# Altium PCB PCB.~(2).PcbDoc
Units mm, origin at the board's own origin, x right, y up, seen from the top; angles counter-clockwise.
Board outline 75.31 x 77.22 mm, 2 copper layers (Top Layer, Bottom Layer); 67 components, 24 nets, 314 pads, 26 vias.
Unrouted connection lines stored in the file: 1.
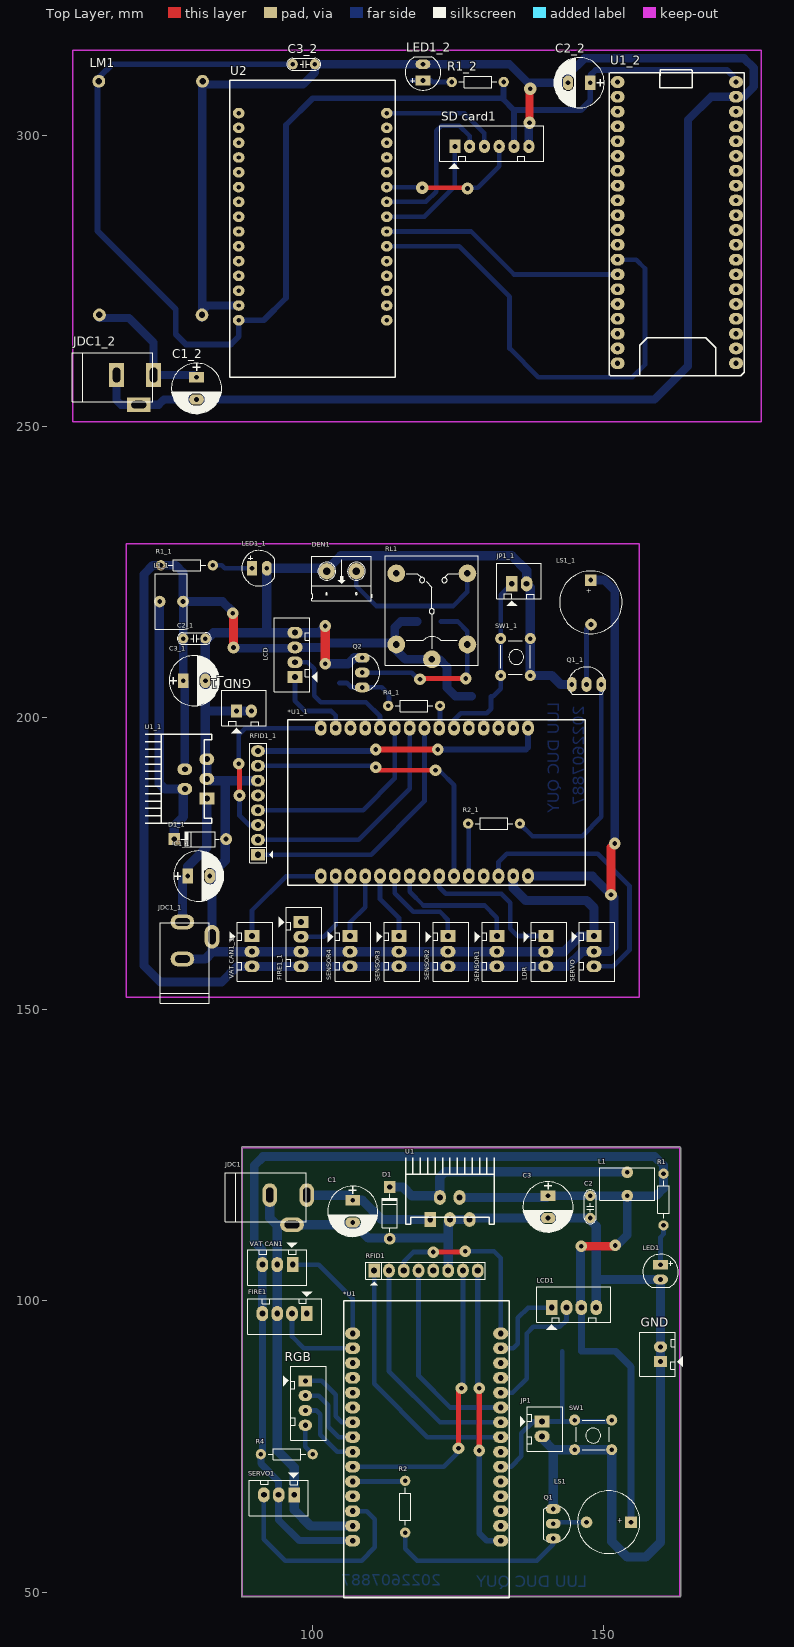
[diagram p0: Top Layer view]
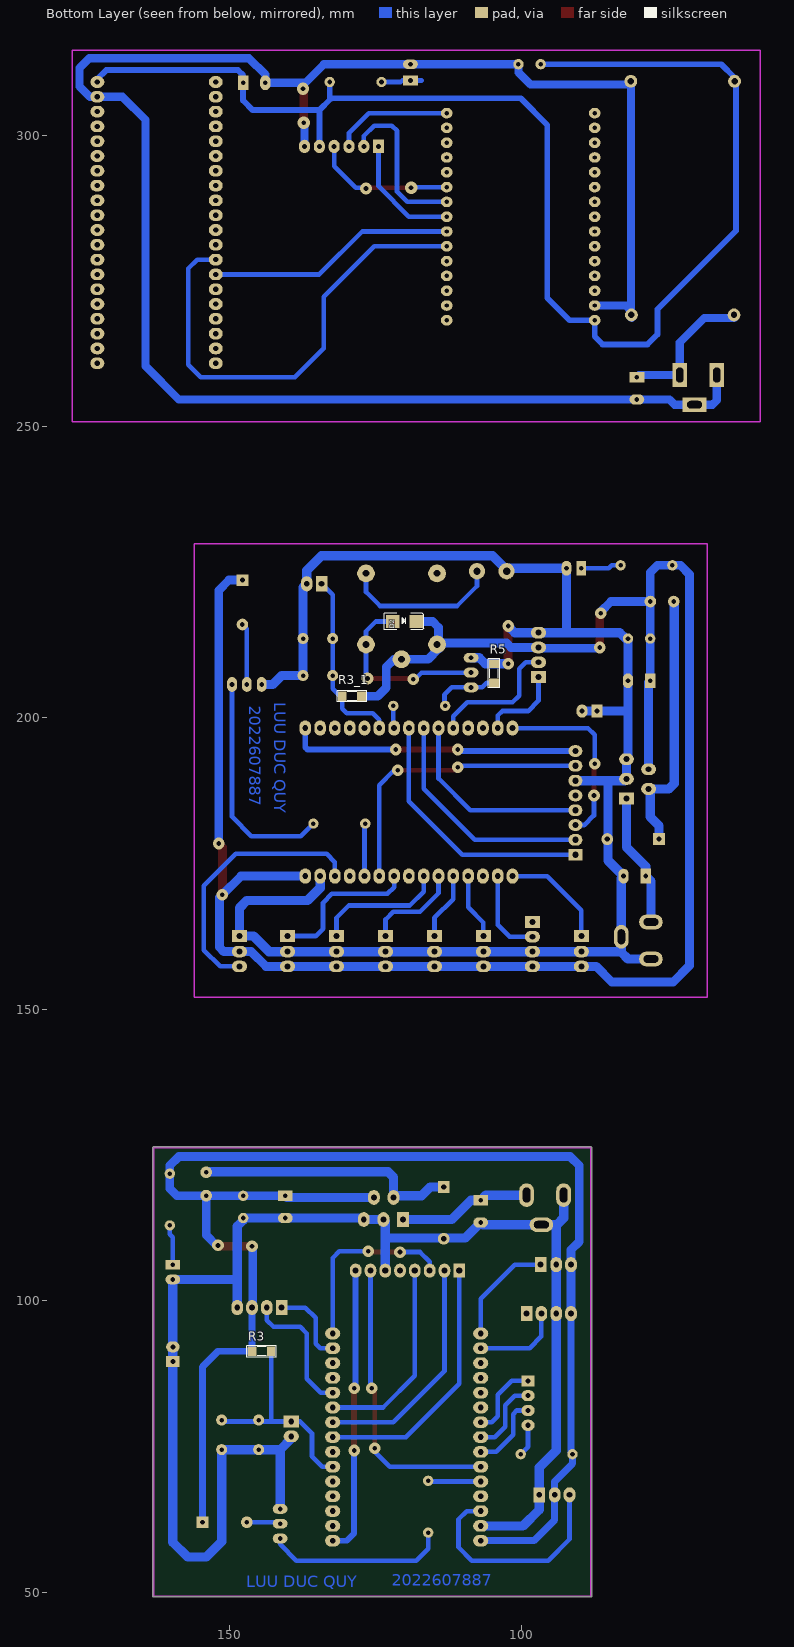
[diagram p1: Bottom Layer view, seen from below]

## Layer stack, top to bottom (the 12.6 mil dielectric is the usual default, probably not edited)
Top Solder: solder mask 0.0102, Solder Resist, Dk 3.5
Top Layer: signal copper 0.0356
Dielectric 1: dielectric 0.32, FR-4, Dk 4.8
Bottom Layer: signal copper 0.0356
Bottom Solder: solder mask 0.0102, Solder Resist, Dk 3.5

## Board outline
87.884,49.276 ccw(c88.011,49.276) 88.011,49.149 163.068,49.149 ccw(c163.068,49.276) 163.195,49.276 163.195,126.238 ccw(c163.068,126.238) 163.068,126.365 88.011,126.365 ccw(c88.011,126.238) 87.884,126.238

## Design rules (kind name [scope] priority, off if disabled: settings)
Clearance [All] p1: gap=0.254 ignorepadtopadclearanceinfootprint=FALSE except(0: Arc-Hole Track-Hole SMDPad-Hole THPad-Hole Via-Hole Fill-Hole Poly-Hole Region-Hole Text-Hole)
PolygonConnect [All] p1: connectstyle=Relief reliefconductorwidth=0.254 reliefentries=4 polygonreliefangle="90 Angle" airgapwidth=0.254
RoutingVias [All] p1: holewidth=0.711 width=1.27 viastyle="Through Hole" minholewidth=0.711 minwidth=1.27 maxholewidth=0.711 maxwidth=1.27
SolderMaskExpansion [All] p1: expansion=0.102
Width GND [InNet('GND')] p1: maxlimit=1.6 minlimit=0.254 preferedwidth=1.6
Width 12V [InNet('12V')] p2: maxlimit=1.6 minlimit=0.254 preferedwidth=1.6
Width 3V3 [InNet('3V3')] p3: maxlimit=1 minlimit=0.254 preferedwidth=1
Width 5V [InNet('5V')] p4: maxlimit=3 minlimit=0.254 preferedwidth=1.2
Width NET [All] p5: maxlimit=3 minlimit=0.254 preferedwidth=0.8
30 further rules are at their usual default settings.

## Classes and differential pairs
component class schematic: *U1 C1 C2 C3 D1 FIRE1 GND JDC1 JP1 L1 LCD1 LED1 LS1 Q1 R1 R2 R3 R4 RFID1 RGB SERVO1 SW1 U1 "VAT CAN1"

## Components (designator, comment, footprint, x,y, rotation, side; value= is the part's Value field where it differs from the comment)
*U1 "*ESP32 module" "ESP32 Module 30PIN"#1 129.794,58.801 r90 top
*U1_1 "*ESP32 module" "ESP32 Module 30PIN"#1 137.033,195.707 r180 top (schematic designator *U1)
C1 "1000uF/16V" CP1.5/3.4 106.934,117.221 r270 top
C1_1 "1000uF/16V" CP1.5/3.4 78.613,172.847 r0 top (schematic designator C1)
C1_2 "1000uF/16V" CP1.5/3.4 80.137,258.445 r270 top (schematic designator C1)
C2 "103" CN1.5 147.701,114.173 r90 top value=0.01uF
C2_1 "103" CN1.5 81.661,213.614 r180 top value=0.01uF (schematic designator C2)
C2_2 "1000uF/16V" CP1.5/3.4 147.701,308.991 r180 top (schematic designator C2)
C3 "1000uF/16V" CP1.5/3.4 140.462,117.983 r270 top
C3_1 "1000uF/16V" CP1.5/3.4 77.851,206.375 r0 top (schematic designator C3)
C3_2 "103" CN1.5 100.457,312.166 r180 top value=0.01uF (schematic designator C3)
D1 "1N4007" D1A 113.284,110.617 r270 top
D1_1 "1N4007" D1A 85.217,179.197 r0 top (schematic designator D1)
D2 "1N4007" DIO-SMD-106 120.015,216.535 r0 bottom
DEN1 "Header 2" HED2 107.569,225.171 r180 top
FIRE1 "JP4" CON4#1 99.06,97.769 r180 top value="Connector 4"
FIRE1_1 "JP4" CON4#1 98.065,164.973 r270 top value="Connector 4" (schematic designator FIRE1)
GND "JP2" CON2#1 159.766,89.535 r90 top value="Connector 2"
GND_1 "JP2" CON2#1 86.995,201.168 r0 top value="Connector 2" (schematic designator GND)
JDC1 "Jac DC" DC0 95.885,115.57 r0 top
JDC1_1 "Jac DC" DC0 80.264,161.798 r90 top (schematic designator JDC1)
JDC1_2 "Jac DC" DC-IN 69.596,256.286 r0 top (schematic designator JDC1)
JP1 "JP2" CON2#2 139.446,79.248 r270 top value="Connector 2"
JP1_1 "JP2" CON2#2 134.239,223.012 r0 top value="Connector 2" (schematic designator JP1)
L1 "L-DIP-1" L-DIP-M-9.5x5.5 154.051,120.015 r270 top value="150 mH"
L1_1 "L-DIP-1" L-DIP-M-9.5x5.5 75.819,219.964 r0 top value="150 mH" (schematic designator L1)
LCD "JP4" CON4#1 97.028,207.01 r90 top value="Connector 4"
LCD1 "JP4" CON4#1 141.097,98.806 r0 top value="Connector 4"
LDR "JP3" CON3 140.081,162.433 r270 top value="Connector 3"
LED1 "LED" LED-5-Green 159.766,106.172 r270 top value="LED 3 ly Single Colour"
LED1_1 "LED" LED-5-Green 89.662,225.679 r0 top value="LED 3 ly Single Colour" (schematic designator LED1)
LED1_2 "LED" LED-5-BLUE 118.999,310.769 r90 top value="LED 3 ly Single Colour" (schematic designator LED1)
LM1 "LM2596 module" LM2596module 81.073,269.145 r90 top
LS1 "Speaker" SPEAKER 154.686,61.976 r180 top
LS1_1 "Speaker" SPEAKER 147.815,223.647 r270 top (schematic designator LS1)
Q1 "C1815" QTO-92 141.351,61.722 r270 top
Q1_1 "C1815" QTO-92 147.066,205.74 r0 top (schematic designator Q1)
Q2 "C1815" QTO-92 108.585,207.772 r270 top
R1 "1k" R1/4W 160.274,121.793 r270 top value="R1/4W - 1K"
R1_1 "1k" R1/4W 74.041,226.187 r0 top value="R1/4W - 1K" (schematic designator R1)
R1_2 "1k" R1/4W 123.952,309.118 r0 top value="R1/4W - 1K" (schematic designator R1)
R2 "1k" R1/4W 115.951,69.088 r270 top value="R1/4W - 1K"
R2_1 "1k" R1/4W 126.746,181.864 r0 top value="R1/4W - 1K" (schematic designator R2)
R3 "10k" SM-RES-1206 142.875,91.313 r0 bottom value="R1/4W - 1K"
R3_1 "10k" SM-RES-1206 130.683,203.708 r180 bottom value="R1/4W - 1K" (schematic designator R3)
R4 "330r" R1/4W 91.186,73.66 r0 top value="R1/4W - 1K"
R4_1 "1k" R1/4W 121.92,202.057 r180 top value="R1/4W - 1K" (schematic designator R4)
R5 "10k" SM-RES-1206 104.648,209.296 r270 bottom value="R1/4W - 1K"
RFID1 "RFID RC522" JP8 110.617,105.156 r0 top
RFID1_1 "RFID RC522" JP8 90.678,176.53 r90 top (schematic designator RFID1)
RGB "JP4" CON4#2 98.806,86.233 r270 top value="Connector 4"
RL1 "Relay 10A/12V" RL_SPDT_10A 120.523,210.058 r90 top value="Relay SPDT, 10A, 12V"
"SD card1" "JP6" CON6 124.46,298.069 r0 top value="Connector 6"
SENSOR1 "JP3" CON3 131.678,162.433 r270 top value="Connector 3"
SENSOR2 "JP3" CON3 123.275,162.433 r270 top value="Connector 3"
SENSOR3 "JP3" CON3 114.872,162.433 r270 top value="Connector 3"
SENSOR4 "JP3" CON3 106.468,162.433 r270 top value="Connector 3"
SERVO "JP3" CON3 148.336,162.433 r270 top value="Connector 3"
SERVO1 "JP3" CON3 96.774,66.675 r180 top value="Connector 3"
SW1 "SW" SW4 151.384,74.422 r180 top value="Button chip 4 pin"
SW1_1 "SW" SW4 137.414,213.614 r270 top value="Button chip 4 pin" (schematic designator SW1)
U1 "LM2576" DIP5-T 123.596,118.161 r0 top
U1_1 "LM2576" DIP5-T 77.673,189.509 r90 top (schematic designator U1)
U1_2 "TANG NANO 20K" "TANG NANO" 152.4,258.318 r0 top (schematic designator U1)
U2 "*ESP32 module" "ESP32 Module 30PIN"#2 110.236,268.224 r90 top
"VAT CAN1" "JP3" CON3 96.52,106.172 r180 top value="Connector 3"
"VAT CAN1_1" "JP3" CON3 89.662,162.433 r270 top value="Connector 3" (schematic designator "VAT CAN1")

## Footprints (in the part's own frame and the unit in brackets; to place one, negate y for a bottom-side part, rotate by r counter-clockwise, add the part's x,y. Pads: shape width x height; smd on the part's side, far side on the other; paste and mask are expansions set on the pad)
CN1.5 [mil]
  round 70 hole 31: 1(0,0) 2(150,0)
  silkscreen extent -40,-40 190,40, body extent -40,-33 190,33, height 235
CON2#1 [mil] "CON2"
  rect 75x90 hole 34: 1(0,0)
  oval 75x90 hole 34: 2(100,0)
  silkscreen extent -100,-150 200,140, body extent -68,-70 168,107, height 236
CON2#2 [mil] "CON2"
  rect 78.74x102.36 hole 39.37: 1(0,0)
  oval 78.74x102.36 hole 39.37: 2(100,0)
  silkscreen extent -100,-150 200,140, body extent -68,-70 168,107, height 236
CON3 [mm] "CON 3"
  rect 2x2.6 hole 1: 1(-0.127,0)
  oval 2x2.6 hole 1: 2(2.54,0) 3(5.08,0)
  silkscreen extent -2.54,-3.8 7.62,3.56, body extent -2.41,-2.29 7.49,3.46, height 7
CON4#1 [mm] "CON4"
  rect 2x2.6 hole 1: 1(0,0)
  oval 2x2.6 hole 1: 2(2.54,0) 3(5.08,0) 4(7.62,0)
  silkscreen extent -2.54,-3.8 10.16,3.56, body extent -2.29,-2.29 10.11,3.46, height 7
CON4#2 [mm] "CON4"
  rect 1.905x2.286 hole 0.864: 1(0,0)
  oval 1.905x2.286 hole 0.864: 2(2.54,0) 3(5.08,0) 4(7.62,0)
  silkscreen extent -2.54,-3.8 10.16,3.56, body extent -2.29,-2.29 10.11,3.46, height 7
CON6 [mil] "CON6"
  rect 75x90 hole 34: 1(0,0)
  oval 75x90 hole 34: 2(100,0) 3(200,0) 4(300,0) 5(400,0) 6(500,0)
  silkscreen extent -100,-150 600,140
CP1.5/3.4 [mil] "Tu hoa 220->470uF,16V, 470uF/16V,25V"
  rect 70x100 hole 32: 1(0,0)
  oval 70x100 hole 32: 2(150,0)
  silkscreen extent -95,-170 245,170, body extent -85,-157 230,157, height 446
D1A [mil] "Diode 1A, W 100mil, L 350mil"
  round 80 hole 35: 1(0,0)
  rect 80x80 hole 35: 2(-350,0)
  silkscreen extent -305,-50 -45,50, body extent -386,-33 34,36, height 84
DC0 [mil] "Jac DC input"
  oval 100x160 hole 50 slot 100 at 90 deg: 1(125,100) 2(-125,100)
  oval 160x100 hole 50 slot 100 at 0 deg: 3(25,-100)
  silkscreen extent -425,-80 120,250, body extent -410,-105 134,269, height 434
DC-IN [mil] "Jac DC input"
  rect 100x160 hole 50 slot 100 at 90 deg: 1(125,100) 2(-125,100)
  rect 160x100 hole 50 slot 100 at 0 deg: 3(25,-100)
  silkscreen extent -425,-80 120,250, body extent -410,-105 134,269, height 434
DIO-SMD-106 [mil]
  rect 90x90.55 smd: 1(80,0) 2(-80,0)
  silkscreen extent -130,-55 135,55, body extent -99,-50 106,52, height 95
DIP5-T [mil]
  rect 80x100 hole 40: 1(-132,-167.09)
  oval 80x100 hole 40: 2(-67,-18) 3(1,-167) 4(66,-18) 5(134,-167)
  round 0 all layers, no hole: ""(1,100)
  silkscreen extent -299,-200 301,250, body extent -199,-175 201,150, height 859
"ESP32 Module 30PIN"#1 [mm]
  oval 2x2.6 hole 1 unplated: 1(0,-2.54) 2(2.54,-2.54) 3(5.08,-2.54) 4(7.62,-2.54) 5(10.16,-2.54) 6(12.7,-2.54) 7(15.24,-2.54) 8(17.78,-2.54) 9(20.32,-2.54) 10(22.86,-2.54) 11(25.4,-2.54) 12(27.94,-2.54) 13(30.48,-2.54) 14(33.02,-2.54) 15(35.56,-2.54) 16(35.56,22.86) 17(33.02,22.86) 18(30.48,22.86) 19(27.94,22.86) 20(25.4,22.86) 21(22.86,22.86) 22(20.32,22.86) 23(17.78,22.86) 24(15.24,22.86) 25(12.7,22.86) 26(10.16,22.86) 27(7.62,22.86) 28(5.08,22.86) 29(2.54,22.86) 30(0,22.86)
  silkscreen extent -9.8,-4 41.2,24.4, body extent -9.9,-4.15 41.03,24.35, height 10.2
"ESP32 Module 30PIN"#2 [mm]
  oval 1.8x2 hole 0.762 unplated: 1(0,-2.54) 2(2.54,-2.54) 3(5.08,-2.54) 4(7.62,-2.54) 5(10.16,-2.54) 6(12.7,-2.54) 7(15.24,-2.54) 8(17.78,-2.54) 9(20.32,-2.54) 10(22.86,-2.54) 11(25.4,-2.54) 12(27.94,-2.54) 13(30.48,-2.54) 14(33.02,-2.54) 15(35.56,-2.54) 16(35.56,22.86) 17(33.02,22.86) 18(30.48,22.86) 19(27.94,22.86) 20(25.4,22.86) 21(22.86,22.86) 22(20.32,22.86) 23(17.78,22.86) 24(15.24,22.86) 25(12.7,22.86) 26(10.16,22.86) 27(7.62,22.86) 28(5.08,22.86) 29(2.54,22.86) 30(0,22.86)
  silkscreen extent -9.8,-4 41.2,24.4, body extent -9.9,-4.15 41.03,24.35, height 10.2
HED2 [mil] "Header 2, 2 pin, hight 300mil, Pin to Pin 200, Colour Green"
  round 110 hole 50: 1(0,0) 2(200,0)
  silkscreen extent -106,-100 300,200, body extent -92,-140 302,155, height 394
JP8 [mm] "JP8"
  rect 2x2.4 hole 1.067: 1(0,0)
  oval 2x2.4 hole 1.067: 2(2.54,0) 3(5.08,0) 4(7.62,0) 5(10.16,0) 6(12.7,0) 7(15.24,0) 8(17.78,0)
  silkscreen extent -1.42,-2.54 19.1,1.45, body extent -1.22,-1.27 19,1.23, height 8.22
L-DIP-M-9.5x5.5 [mm] "Body 9.5x5.5mm, 2 leads"
  round 2 hole 0.8: 1(-2,0) 2(2,0)
  silkscreen extent -2.75,-4.75 2.75,4.75, body extent -2.57,-5.05 2.57,5.05, height 10.07
LED-5-BLUE [mil] "LED 2 PIN, 5 ly , Only colour, pin to pin 110mil"
  rect 65x100 hole 32: 1(-55,0)
  oval 65x100 hole 32: 2(55,0)
  silkscreen extent -120,-120 104,120, body extent -113,-120 100,117, height 339
LED-5-Green [mil] "LED 2 PIN, 5 ly , Only colour,pin to pin 100mil"
  rect 65x100 hole 32: 1(0,0)
  oval 65x100 hole 32: 2(100,0)
  silkscreen extent -70,-120 154,120, body extent -69,-120 145,117, height 339
LM2596module [mm]
  round 2.2 hole 1.1: 1(0,17.6) 2(0,0) 3(40.1,-0.1) 4(40.1,17.7)
  body extent -1.6,-1.8 41.7,19.5, height 12.95
QTO-92 [mil] "TO-92"
  oval 66x100 hole 32: 1(-100,0) 2(0,0) 3(100,0)
  silkscreen extent -117,-65 120,118, body extent -109,-66 109,95, height 245
R1/4W [mil] "R 1/4W, 2 Pin, 350mil"
  round 70 hole 31: 1(0,0) 2(350,0)
  silkscreen extent 48,-38 302,38, body extent -40,-47 386,47, height 111
RL_SPDT_10A [mil] "Relay SPDT, 5 pin, 10A,W 650mil, L 800mil, H 800mil"
  round 120 hole 45: 1(0,0) 2(580,240) 3(580,-240) 4(100,-240) 5(100,240)
  silkscreen extent -40,-315 700,315, body extent -46,-304 706,306, height 602
SM-RES-1206 [mil]
  rect 60x65 smd: 1(0,0) 2(130,0)
  silkscreen extent -34,-38 164,39, body extent 2,-31 128,31, height 40
SPEAKER [mm]
  rect 2x2 hole 0.8: 1(0,0)
  round 2 hole 0.8: 2(7.62,0.013)
  silkscreen extent -1.55,-5.38 9.18,5.36, body extent -2.22,-6 13.24,6, height 4.5
SW4 [mil] "SW button 4pin, 250 x250 mil"
  round 75 hole 31: 1(0,0) 2(250,-200) 3(250,0) 4(0,-200)
  silkscreen extent 15,-215 240,0, body extent -36,-220 276,24, height 276
"TANG NANO" [mm]
  oval 2.4x2 hole 0.9: 1(0,50.8) 2(0,48.26) 3(0,45.72) 4(0,43.18) 5(0,40.64) 6(0,38.1) 7(0,35.56) 8(0,33.02) 9(0,30.48) 10(0,27.94) 11(0,25.4) 12(0,22.86) 13(0,20.32) 14(0,17.78) 15(0,15.24) 16(0,12.7) 17(0,10.16) 18(0,7.62) 19(0,5.08) 20(0,2.54) 21(20.32,2.54) 22(20.32,5.08) 23(20.32,7.62) 24(20.32,10.16) 25(20.32,12.7) 26(20.32,15.24) 27(20.32,17.78) 28(20.32,20.32) 29(20.32,22.86) 30(20.32,25.4) 31(20.32,27.94) 32(20.32,30.48) 33(20.32,33.02) 34(20.32,35.56) 35(20.32,38.1) 36(20.32,40.64) 37(20.32,43.18) 38(20.32,45.72) 39(20.32,48.26) 40(20.32,50.8)
  silkscreen extent -1.4,0.4 21.7,52.9

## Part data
*U1 *U1_1 U2: library part "ESP32 module"
C1 C1_1 C1_2 C2_2 C3 C3_1: library part CP4, "Cap 1000uF/16V - 220uF/50V"
C2 C2_1 C3_2: library part CN1.5, "Cap np 682pF => 104pF"
D1 D1_1 D2: library part D1A, "Diode 1A"
DEN1: library part Hed2, "Header 2 (Green)"
FIRE1 FIRE1_1 LCD LCD1 RGB: library part Con4, "Connector 4"
GND GND_1 JP1 JP1_1: library part Con2, "Connector 2"
JDC1 JDC1_1 JDC1_2: library part DCIN, "Jac DC input"
L1 L1_1: "Inductor"
LDR SENSOR1 SENSOR2 SENSOR3 SENSOR4 SERVO SERVO1 "VAT CAN1" "VAT CAN1_1": library part Con3, "Connector 3"
LED1 LED1_1 LED1_2: "LED Single colour Green and Red"
LS1 LS1_1: "Loudspeaker"
Q1 Q1_1 Q2: "NPN 600mW, ECB"
R1 R1_1 R1_2 R2 R2_1 R4 R4_1: library part R1/4W, "Resistor 1/4W"
R3 R3_1 R5: library part R, "Resistor 1/4W"
RL1: library part "Relay 1", "Relay SPDT,10A - 12VDC 5 Pin"
"SD card1": library part Con6, "Connector 6"
SW1 SW1_1: library part SW4, "Switch button 4 pin"
U1 U1_1: Max Input Voltage="12 V", Max Output Current="3 (6.0 peak) A", Max Output Voltage=mV, Temperature Range="-40 to +125 degC"
U1_2: library part "Tang nano 20K"

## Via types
v1: diameter 2, hole 0.8, Top Layer to Bottom Layer, 22 vias
v2: diameter 2.1, hole 0.82, Top Layer to Bottom Layer, 4 vias

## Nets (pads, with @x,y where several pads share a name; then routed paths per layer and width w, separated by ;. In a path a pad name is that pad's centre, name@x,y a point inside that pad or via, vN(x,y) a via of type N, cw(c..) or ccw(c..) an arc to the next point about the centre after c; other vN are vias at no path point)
3V3: *U1.1 RFID1.8 | length 48.4
  Top Layer w1: v1(128.651,74.295) v1(128.651,84.963)
  Bottom Layer w1: v1@128.397,85.344 RFID1.8 ; v1@128.651,73.787 128.651,60.071 129.921,58.801 *U1.1
5V: "VAT CAN1.3" *U1.30 C2.2 C3.1 FIRE1.4 L1.2 LCD1.3 LS1.1 R1.1 R3.2 R4.1 SERVO1.2 U1.4 | length 256.9
  Top Layer w1.5: v1(146.177,109.347) 151.892,109.347 v1(152.019,109.474)
  Bottom Layer w1.2: FIRE1.4 91.44,73.914 R4.1 91.186,72.009 94.234,68.961 SERVO1.2 94.234,62.357 97.79,58.801 *U1.30 ; LCD1.3 R3.2 152.019,91.313 154.686,88.646 LS1.1
  Bottom Layer w1.5: FIRE1.4 91.44,106.172 91.44,108.712 90.043,110.109 90.043,123.19 91.567,124.714 158.75,124.714 160.274,123.19 R1.1 160.274,119.253 159.036,118.015 L1.2 ; U1.4 140.183,117.704 C3.1 C2.2 154.019,117.983 L1.2 ; v1@146.047,108.715 146.047,98.936 LCD1.3 ; v1@152.273,109.474 154.051,111.252 L1.2
12V: C1.1 JDC1.1 U1.1 | length 22.9
  Bottom Layer w1.6: JDC1.1 106.045,118.11 C1.1 108.585,117.221 111.889,113.917 U1.1
B_PIN: *U1.22 RGB.1 | length 13.2
  Bottom Layer w0.8: RGB.1 101.6,86.233 104.013,83.82 104.013,80.137 105.029,79.121 *U1.22
Buzzer: *U1.26 R2.1 | length 9.1
  Bottom Layer w0.8: *U1.26 115.824,68.961 R2.1
G_PIN: *U1.24 RGB.3 | length 13.2
  Bottom Layer w0.8: RGB.3 100.711,81.153 101.346,80.518 101.346,76.962 104.267,74.041 *U1.24
GND: "VAT CAN1.2" *U1.29 C1.2 C2.1 C3.2 D1.1 FIRE1.3 GND.1 GND.2 JDC1.2 JDC1.3 JP1.2 LCD1.4 LED1.2 Q1.1 RFID1.6 SERVO1.1 SW1.1 SW1.3 U1.3 U1.5 | length 252.3
  Bottom Layer w1.6: JDC1.2 92.71,114.173 93.853,113.03 94.234,113.03 ; *U1.29 99.695,61.341 96.901,64.135 SERVO1.1 96.901,71.374 93.98,74.295 FIRE1.3 93.98,106.172 93.98,112.776 94.234,113.03 ; RFID1.6 123.317,110.744 ; JP1.2 139.446,76.327 141.351,74.422 ; Q1.1 141.351,74.422 ; LCD1.4 148.717,103.378 ; 94.234,113.03 JDC1.3 106.553,113.03 C1.2 109.601,110.744 123.317,110.744 ; 123.317,110.744 123.317,113.614 U1.3 U1.5 127.254,114.173 C3.2 C2.1 147.701,113.792 148.717,112.776 148.717,103.378 ; 141.351,74.422 SW1.3 SW1.1 151.384,58.674 154.051,56.007 157.226,56.007 159.766,58.547 GND.1 GND.2 LED1.2 148.971,103.632 148.717,103.378
LCD_SCL: *U1.14 LCD1.1 | length 14.3
  Bottom Layer w0.8: *U1.14 134.493,91.821 135.255,92.583 135.255,97.028 137.033,98.806 LCD1.1
LCD_SDA: *U1.11 LCD1.2 | length 23.2
  Bottom Layer w0.8: *U1.11 134.366,84.201 136.779,86.614 136.779,94.361 137.922,95.504 142.494,95.504 143.637,96.647 LCD1.2
NetD1_2: D1.2 L1.1 U1.2 | length 45.5
  Bottom Layer w1.6: D1.2 115.57,119.507 117.094,117.983 121.615,117.983 U1.2 121.895,121.158 122.841,122.105 154.051,122.105 L1.1
NetLED1_1: LED1.1 R1.2 | length 6.9
  Bottom Layer w0.8: LED1.1 159.766,110.871 160.274,111.379 R1.2
NetLS1_2: LS1.2 Q1.2 | length 5.8
  Bottom Layer w0.8: Q1.2 141.592,61.963 LS1.2
NetQ1_3: Q1.3 R2.2 | length 31.2
  Bottom Layer w0.8: R2.2 115.951,57.404 117.983,55.372 138.557,55.372 141.351,58.166 Q1.3
NetR4_2: R4.2 RGB.4 | length 5.5
  Bottom Layer w0.8: RGB.4 98.806,74.93 R4.2
"PIN_BTN MANUAL": *U1.6 JP1.1 R3.1 SW1.2 SW1.4 | length 36.5
  Bottom Layer w0.8: *U1.6 134.112,71.501 135.89,73.279 135.89,77.216 137.922,79.248 JP1.1 142.875,79.248 ; R3.1 142.875,79.248 ; SW1.4@151.257,79.248 142.875,79.248
PIN_FIRE: *U1.17 FIRE1.2 | length 15.2
  Bottom Layer w0.8: FIRE1.2 96.52,93.853 98.552,91.821 *U1.17
PIN_VATCAN: "VAT CAN1.1" *U1.19 | length 18.7
  Bottom Layer w0.8: 96.647,106.172 101.092,106.172 106.934,100.33 106.934,94.361
R_PIN: *U1.23 RGB.2 | length 13.2
  Bottom Layer w0.8: RGB.2 101.092,83.693 102.743,82.042 102.743,78.359 104.521,76.581 *U1.23
RFID_MISO: *U1.10 RFID1.4 | length 34.4
  Bottom Layer w0.8: RFID1.4 118.237,87.122 123.698,81.661 *U1.10
RFID_MOSI: *U1.15 RFID1.3 | length 32.3
  Top Layer w0.8: v1(120.777,108.331) 126.111,108.331 v1(126.238,108.458)
  Bottom Layer w0.8: RFID1.3 115.697,106.68 117.348,108.331 v1(120.777,108.331) ; v1(126.238,108.458) 131.191,108.458 132.334,107.315 *U1.15
RFID_RST: *U1.25 RFID1.7 | length 50.7
  Top Layer w0.8: v1(125.095,74.676) 125.095,84.455 v1(125.603,84.963)
  Bottom Layer w0.8: *U1.25 122.555,71.501 124.968,73.914 v1@124.968,74.676 ; v1@125.857,84.709 RFID1.7
RFID_SCK: *U1.9 RFID1.2 | length 40.1
  Bottom Layer w0.8: RFID1.2 113.157,87.884 121.92,79.121 *U1.9
RFID_SS: *U1.8 RFID1.1 | length 44.9
  Bottom Layer w0.8: RFID1.1 110.617,85.725 119.761,76.581 *U1.8
servo: *U1.28 SERVO1.3 | length 38.4
  Bottom Layer w0.8: SERVO1.3 91.694,59.055 95.377,55.372 108.458,55.372 110.744,57.658 110.744,62.484 109.347,63.881 *U1.28
pads on no net: "SD card1.1" "SD card1.2" "SD card1.3" "SD card1.4" "SD card1.5" "SD card1.6" "VAT CAN1_1.1" "VAT CAN1_1.2" "VAT CAN1_1.3" *U1.2 *U1.3 *U1.4 *U1.5 *U1.7 *U1.12 *U1.13 *U1.16 *U1.18 *U1.20 *U1.21 *U1.27 *U1_1.1 *U1_1.2 *U1_1.3 *U1_1.4 *U1_1.5 *U1_1.6 *U1_1.7 *U1_1.8 *U1_1.9 *U1_1.10 *U1_1.11 *U1_1.12 *U1_1.13 *U1_1.14 *U1_1.15 *U1_1.16 *U1_1.17 *U1_1.18 *U1_1.19 *U1_1.20 *U1_1.21 *U1_1.22 *U1_1.23 *U1_1.24 *U1_1.25 *U1_1.26 *U1_1.27 *U1_1.28 *U1_1.29 *U1_1.30 C1_1.1 C1_1.2 C1_2.1 C1_2.2 C2_1.1 C2_1.2 C2_2.1 C2_2.2 C3_1.1 C3_1.2 C3_2.1 C3_2.2 D1_1.1 D1_1.2 D2.1 D2.2 DEN1.1 DEN1.2 FIRE1.1 FIRE1_1.1 FIRE1_1.2 FIRE1_1.3 FIRE1_1.4 GND_1.1 GND_1.2 JDC1_1.1 JDC1_1.2 JDC1_1.3 JDC1_2.1 JDC1_2.2 JDC1_2.3 JP1_1.1 JP1_1.2 L1_1.1 L1_1.2 LCD.1 LCD.2 LCD.3 LCD.4 LDR.1 LDR.2 LDR.3 LED1_1.1 LED1_1.2 LED1_2.1 LED1_2.2 LM1.1 LM1.2 LM1.3 LM1.4 LS1_1.1 LS1_1.2 Q1_1.1 Q1_1.2 Q1_1.3 Q2.1 Q2.2 Q2.3 R1_1.1 R1_1.2 R1_2.1 R1_2.2 R2_1.1 R2_1.2 R3_1.1 R3_1.2 R4_1.1 R4_1.2 R5.1 R5.2 RFID1.5 RFID1_1.1 RFID1_1.2 RFID1_1.3 RFID1_1.4 RFID1_1.5 RFID1_1.6 RFID1_1.7 RFID1_1.8 RL1.1 RL1.2 RL1.3 RL1.4 RL1.5 SENSOR1.1 SENSOR1.2 SENSOR1.3 SENSOR2.1 SENSOR2.2 SENSOR2.3 SENSOR3.1 SENSOR3.2 SENSOR3.3 SENSOR4.1 SENSOR4.2 SENSOR4.3 SERVO.1 SERVO.2 SERVO.3 SW1_1.1 SW1_1.2 SW1_1.3 SW1_1.4 U1. U1_1. U1_1.1 U1_1.2 U1_1.3 U1_1.4 U1_1.5 U1_2.1 U1_2.2 U1_2.3 U1_2.4 U1_2.5 U1_2.6 U1_2.7 U1_2.8 U1_2.9 U1_2.10 U1_2.11 U1_2.12 U1_2.13 U1_2.14 U1_2.15 U1_2.16 U1_2.17 U1_2.18 U1_2.19 U1_2.20 U1_2.21 U1_2.22 U1_2.23 U1_2.24 U1_2.25 U1_2.26 U1_2.27 U1_2.28 U1_2.29 U1_2.30 U1_2.31 U1_2.32 U1_2.33 U1_2.34 U1_2.35 U1_2.36 U1_2.37 U1_2.38 U1_2.39 U1_2.40 U2.1 U2.2 U2.3 U2.4 U2.5 U2.6 U2.7 U2.8 U2.9 U2.10 U2.11 U2.12 U2.13 U2.14 U2.15 U2.16 U2.17 U2.18 U2.19 U2.20 U2.21 U2.22 U2.23 U2.24 U2.25 U2.26 U2.27 U2.28 U2.29 U2.30
copper on no net: | length 2132.7
  Top Layer w0.8: v1(87.376,192.151) 87.503,192.024 v1(87.503,186.69) ; v1(110.871,191.516) 111.379,191.008 v1(121.158,191.008) ; v1(118.491,206.629) 118.618,206.756 v1(126.365,206.756) ; v2(118.872,290.957) 126.492,290.957 v2(126.619,290.83)
  Top Layer w1: v1(110.871,194.564) v1(121.539,194.564)
  Top Layer w1.4: v2(137.287,302.133) 137.287,307.848 v2(137.414,307.975)
  Top Layer w1.5: v1(86.36,217.932) 86.487,217.805 v1(86.487,212.09) ; v1(151.257,169.672) 151.257,177.8 v1(151.892,178.435)
  Top Layer w1.6: v1(102.235,209.296) v1(102.235,215.773)
  Bottom Layer w0.8: 82.931,226.187 84.455,226.187 84.963,225.679 89.662,225.679 ; v1(87.376,192.151) 87.376,197.104 88.519,198.247 101.473,198.247 ; v1(87.503,186.69) 87.503,183.261 89.154,181.61 90.678,181.61 ; 89.662,162.56 89.662,167.005 95.504,172.847 101.473,172.847 ; 90.678,176.53 110.109,176.53 119.253,185.674 119.253,198.247 ; 90.678,179.07 107.95,179.07 116.713,187.833 116.713,198.247 ; 90.678,184.15 108.712,184.15 114.173,189.611 114.173,198.247 ; 90.678,191.77 v1@111.125,191.77 ; 97.028,207.01 97.028,202.946 98.806,201.168 103.251,201.168 104.013,200.406 104.013,198.247 ; 97.028,209.55 99.187,209.55 100.33,208.407 100.33,203.835 101.473,202.692 109.22,202.692 111.633,200.279 111.633,198.247 ; 98.065,162.433 101.981,162.433 104.013,164.465 104.013,172.847 ; 104.648,205.994 105.918,205.994 106.68,205.232 108.585,205.232 111.887,205.232 113.157,203.962 113.157,202.184 113.03,202.057 ; 106.468,162.56 106.468,164.888 109.093,167.513 109.093,172.847 ; 107.569,225.171 107.569,222.631 110.998,219.202 124.206,219.202 126.619,221.615 126.619,224.79 ; 108.585,207.772 117.094,207.772 v1@118.618,206.248 ; 111.633,172.847 111.633,168.91 114.872,165.671 114.872,162.56 ; 112.776,280.924 125.222,280.924 133.858,272.288 133.858,263.398 138.811,258.445 154.94,258.445 157.099,260.604 157.099,277.114 155.575,278.638 152.4,278.638 ; 112.776,283.464 127.254,283.464 134.62,276.098 152.4,276.098 ; 112.776,286.004 119.253,286.004 124.46,291.211 124.46,298.069 ; 112.776,288.544 119.507,288.544 121.285,290.322 121.285,300.736 122.174,301.625 125.222,301.625 127,299.847 127,298.069 ; 112.776,291.084 v2@118.872,291.084 ; 112.776,303.784 126.111,303.784 129.54,300.355 129.54,298.069 ; 114.173,172.847 114.173,169.926 117.348,166.751 121.92,166.751 123.275,165.396 123.275,162.56 ; 116.713,172.847 116.713,170.18 119.088,167.805 129.587,167.805 131.678,165.714 131.678,162.56 ; 117.094,309.372 118.999,309.372 120.396,309.372 120.65,309.118 123.952,309.118 ; v1@121.158,190.881 121.92,190.881 124.333,188.468 124.333,172.847 ; 121.793,172.847 121.793,170.942 122.936,169.799 132.461,169.799 133.985,168.275 133.985,163.83 135.255,162.56 140.081,162.56 ; 121.793,198.247 121.92,198.374 121.92,202.057 ; 122.047,216.535 124.968,216.535 126.619,214.884 126.619,212.598 v1@126.619,206.883 ; 124.333,198.247 124.333,199.644 125.476,200.787 129.921,200.787 130.683,201.549 130.683,203.708 131.064,203.708 132.334,204.978 132.334,207.264 132.334,213.614 132.334,221.107 134.239,223.012 ; v2@126.111,290.957 128.397,290.957 132.08,294.64 132.08,298.069 ; 126.746,181.864 126.873,181.737 126.873,172.847 ; 131.953,172.847 131.953,175.26 133.35,176.657 148.971,176.657 154.432,171.196 154.432,160.147 151.638,157.353 148.336,157.353 ; 135.636,181.864 137.795,179.705 146.304,179.705 149.606,183.007 149.606,205.74 ; 147.066,205.74 147.066,215.265 147.828,216.027
  Bottom Layer w1: 90.678,194.31 v1@110.49,194.31 ; 96.647,312.166 65.659,312.166 63.373,309.88 63.373,309.245 63.119,308.991 63.119,283.591 76.581,270.129 76.581,265.811 78.295,264.096 86.042,264.096 87.376,265.43 87.376,268.224 91.694,268.224 95.504,272.034 95.504,301.752 100.076,306.324 132.715,306.324 ; v1@122.047,194.564 136.652,194.564 137.033,194.945 137.033,198.247 ; 132.842,309.118 132.842,306.451 132.715,306.324 ; 134.62,298.069 134.62,304.292 ; 172.72,309.118 172.72,309.626 171.196,311.15 148.59,311.15 147.701,310.261 147.701,308.991 147.701,305.943 146.05,304.292 134.62,304.292 ; 132.715,306.324 132.715,306.197 134.62,304.292
  Bottom Layer w1.4: 63.426,268.605 68.58,268.605 72.771,264.414 72.771,258.826 79.756,258.826 80.137,258.445 ; 66.421,258.826 66.421,254.508 67.183,253.746 70.231,253.746 73.66,253.746 74.549,254.635 80.137,254.635 158.75,254.635 164.465,260.35 164.465,302.641 168.402,306.578 172.72,306.578 173.99,306.578 175.768,308.356 175.768,311.531 174.117,313.182 146.685,313.182 143.891,310.388 143.891,308.991 137.033,308.991 133.858,312.166 118.999,312.166 100.457,312.166 100.457,310.769 98.393,308.705 81.126,308.705 81.126,269.848 ; 81.026,268.605 81.126,268.705 81.126,269.848 ; 87.376,270.764 82.042,270.764 81.126,269.848 ; 137.16,298.069 v2@137.16,302.006
  Bottom Layer w1.5: 78.13,191.186 78.13,206.096 77.851,206.375 77.851,213.614 77.851,219.932 77.819,219.964 ; v1@86.36,218.186 84.582,219.964 77.819,219.964 ; v1@87.119,211.96 96.898,211.96 97.028,212.09 101.727,212.09 102.489,212.852 114.173,212.852 ; 117.983,216.535 115.189,216.535 114.173,215.519 114.173,212.852 ; 127.381,203.708 124.587,203.708 123.126,205.168 123.126,208.724 121.793,210.058 120.523,210.058 115.951,210.058 114.173,211.836 114.173,212.852 ; 137.033,172.847 148.082,172.847 v1(151.257,169.672) 151.765,169.164 151.765,160.655 151.003,159.893 148.336,159.893 146.304,159.893 143.764,157.353 140.081,157.353 131.678,157.353 123.275,157.353 114.872,157.353 106.468,157.353 98.065,157.353 89.662,157.353 87.122,157.353 84.455,154.686 73.914,154.686 71.12,157.48 71.12,224.663 72.644,226.187 74.041,226.187 76.581,226.187 77.819,224.949 77.819,219.964 ; 147.815,223.647 150.114,223.647 151.892,221.869 v1@151.892,178.562
  Bottom Layer w1.6: 73.819,219.964 73.729,219.964 73.729,188.754 74.676,187.808 78.13,187.808 77.851,187.528 77.851,183.007 76.327,181.483 76.327,179.197 ; 77.724,158.623 81.661,158.623 82.804,159.766 82.804,160.147 ; 77.724,164.973 77.724,171.958 78.613,172.847 78.613,174.498 81.917,177.802 81.917,186.157 ; 89.535,201.168 86.995,201.168 81.661,201.168 ; 90.678,189.23 85.09,189.23 ; v1(102.235,209.296) 104.648,209.296 106.172,209.296 107.188,210.312 108.585,210.312 ; v1(102.235,215.773) 101.092,214.63 97.028,214.63 92.456,214.63 ; 134.493,172.847 134.493,170.815 136.652,168.656 147.066,168.656 148.336,167.386 148.336,162.56 145.923,162.56 143.256,159.893 140.081,159.893 131.678,159.893 123.275,159.893 114.872,159.893 106.468,159.893 98.065,159.893 89.662,159.893 83.058,159.893 82.804,160.147 ; 144.526,205.74 142.621,205.74 141.097,207.264 137.414,207.264 137.414,213.614 137.414,222.377 136.779,223.012 136.779,225.298 134.239,227.838 104.902,227.838 102.489,225.425 102.489,225.171 101.981,225.679 92.202,225.679 92.202,214.884 92.456,214.63 ; 81.661,201.168 81.661,193.167 81.915,192.913 81.915,189.535 82.22,189.23 85.09,189.23 ; 81.661,201.168 81.661,206.375 81.661,213.614 82.042,213.614 83.058,214.63 92.456,214.63 ; 82.804,160.147 82.804,162.433 82.804,172.466 82.423,172.847 85.09,175.514 85.09,189.23

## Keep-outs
Keep-Out Layer:
  lines w0.254: 58.928,250.825 177.038,250.825 177.038,314.579 58.928,314.579 58.928,250.825 ; 68.072,152.019 68.072,229.87 156.083,229.87 156.083,152.019 68.072,152.019 ; 88.011,49.276 88.011,126.238 163.068,126.238 163.068,49.276 88.011,49.276

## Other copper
Bottom Layer:
  text "LUU DUC QUY" at 142.367,202.692 h2 r90
  text "2022607887" at 146.685,202.057 h2 r90
  text "2022607887" at 122.174,51.054 h2
  text "LUU DUC QUY" at 147.193,50.8 h2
